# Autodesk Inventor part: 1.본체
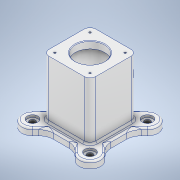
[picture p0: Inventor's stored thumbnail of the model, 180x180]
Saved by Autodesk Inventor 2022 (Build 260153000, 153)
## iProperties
Created: 2022-05
Part Number: 1.본체
Material: 알루미늄 6061
Document SubType Name: Modeling
Designer: Admin
Mass: 1072.62 g
Surface Area: 876.974 cm^2
Volume: 397.266 cm^3
Density: 2.7 g/cm^3
Appearance: 알루미늄 - 평지
Author: Admin
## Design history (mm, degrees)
sketch "스케치1"
  geometry: L1 (40, 40)-(-40, 40); L2 (-40, 40)-(-40, -40); L3 (-40, -40)-(40, -40); L4 (40, -40)-(40, 40); L5 (40, 40)-(-40, -40); L6 (-40, 40)-(40, -40); 1 further point
  constraints: 12 end point, 2 midpoint, 2 parallel, 1 horizontal, 1 perpendicular
  dimensions: "d0" = 80 distance of L3.end L2.end; "d1" = 80 distance of L2.end L1.end
extrude "돌출1" new body sketch "스케치1" distance "d2" = 110; taper "d3" = 0 deg
sketch "스케치2"
  geometry: L1 (40, 40)-(40, -40) reference; L2 (-40, 40)-(40, 40) reference; L3 (-40, -40)-(-40, 40) reference; L4 (40, -40)-(-40, -40) reference; L5 (-104.238, 0)-(104.238, 0) reference; L6 (0, -104.238)-(0, 104.238) reference; L7 (-23.544, 49)-(23.544, 49); L8 (49, 23.544)-(49, -23.544); L9 (23.544, -49)-(-23.544, -49); L10 (-49, -23.544)-(-49, 23.544); L11 (-49, 49)-(49, -49); L12 (49, 49)-(-49, -49); L13 (-49, 49)-(49, -49); L14 (-49, -49)-(49, 49); L15 (49, 23.544)-(61.728, 36.272); L16 (61.728, -36.272)-(49, -23.544); L17 (36.272, 61.728)-(23.544, 49); L18 (-23.544, 49)-(-36.272, 61.728); L19 (-61.728, 36.272)-(-49, 23.544); L20 (-49, -23.544)-(-61.728, -36.272); L21 (-36.272, -61.728)-(-23.544, -49); L22 (23.544, -49)-(36.272, -61.728); A1 r 18 centre (-49, 49) between (-36.272, 61.728) and (-61.728, 36.272); A2 r 18 centre (49, -49) between (36.272, -61.728) and (61.728, -36.272); A3 r 18 centre (-49, -49) between (-61.728, -36.272) and (-36.272, -61.728); A4 r 18 centre (49, 49) between (61.728, 36.272) and (36.272, 61.728); 1 further point
  constraints: 36 end point, 16 tangent, 12 equal length, 8 point on circle, 4 centre point, 4 midpoint, 1 horizontal, 1 perpendicular, 1 point on line
  dimensions: "d7" = 98 distance of L11.end L12.end; "d8" = 98 distance of L12.start L11.end; "d9" = 36 diameter of A2; "d10" = 36 diameter of A4; "d11" = 49 distance between parallel lines of L6 L8; "d12" = 49 distance between parallel lines of L6 L10; "d13" = 98 distance between parallel lines of L7 L9; "d14" = 49 distance between parallel lines of L7 L5; "d15" = 45 deg angle of L5 L14; "d16" = 45 deg angle of L5 L11
extrude "돌출2" join sketch "스케치2" distance "d17" = 12; taper "d18" = 0 deg
sketch "스케치3"
  geometry: L1 (-61.728, -36.272)-(-49, -23.544) reference; L2 (-49, -23.544)-(-49, 23.544) reference; L3 (-49, 23.544)-(-61.728, 36.272) reference; L4 (-36.272, 61.728)-(-23.544, 49) reference; L5 (-23.544, 49)-(23.544, 49) reference; L6 (23.544, 49)-(36.272, 61.728) reference; L7 (61.728, 36.272)-(49, 23.544) reference; L8 (49, 23.544)-(49, -23.544) reference; L9 (49, -23.544)-(61.728, -36.272) reference; L10 (36.272, -61.728)-(23.544, -49) reference; L11 (23.544, -49)-(-23.544, -49) reference; L12 (-23.544, -49)-(-36.272, -61.728) reference; A1 r 18 centre (-49, 49) between (-36.272, 61.728) and (-61.728, 36.272) reference; A2 r 18 centre (49, 49) between (61.728, 36.272) and (36.272, 61.728) reference; A3 r 18 centre (49, -49) between (36.272, -61.728) and (61.728, -36.272) reference; A4 r 18 centre (-49, -49) between (-61.728, -36.272) and (-36.272, -61.728) reference; 5 further points
  constraints: 4 coincident
hole "구멍1" sketch "스케치3" at (49, 49), (49, -49), (-49, 49), (-49, -49) diameter "d19" = 10; stored, may be unused: countersink angle "d23" = 90 deg, drill point angle "d25" = 118 deg; dims "d20" = 11, "d21" = 18, "d22" = 4, "d24" = 13
sketch "스케치4"
  geometry: L1 (40, -132)-(40, 22) reference; L2 (16.456, -98)-(63.544, -98) reference; C1 r 20 at (40, -49); 1 further point
  constraints: 1 centre point, 1 point on line
  dimensions: "d26" = 40 diameter of C1; "d27" = 49 distance from line of L2 C1.centre
extrude "돌출3" join sketch "스케치4" distance "d28" = 15; taper "d29" = 0 deg
sketch "스케치5"
  geometry: C1 r 20 at (0, 0) reference; C2 r 15 at (0, 0); 1 further point
  constraints: 1 centre point, 1 coincident
  dimensions: "d30" = 30 diameter of C2
extrude "돌출4" cut sketch "스케치5" distance "d31" = 8; taper "d32" = 0 deg
sketch "스케치6"
  geometry: L1 (-22, 0)-(132, 0) reference; L2 (0, -93.8)-(0, 93.8) reference; L3 (110, -40)-(110, 40) reference; L4 (110, -25)-(98, -25); L5 (98, -25)-(98, -35); L6 (98, -35)-(12, -35); L7 (12, -35)-(12, -25); L8 (12, -25)-(0, -25); L9 (0, 23.544)-(0, -23.544) reference; L10 (110, -25)-(110, 0); L11 (110, 0)-(0, 0); L12 (0, 0)-(0, -25); 1 further point
  constraints: 16 end point, 4 point on line, 3 perpendicular, 2 collinear, 1 horizontal, 1 midpoint
  dimensions: "d33" = 70 diameter of L6 L1; "d34" = 50 diameter of L8 L1; "d35" = 86 distance of L5.end L6.end; "d36" = 12 distance of L4.start L4.end
revolve "회전1" sketch "스케치6" stored, may be unused: angle "d37" = 90 deg
sketch "스케치7"
  geometry: C1 r 15 at (0, 0) reference; C2 r 15 at (0, 0) reference; C3 r 12.5 at (0, 0); 1 further point
  constraints: 1 centre point, 1 coincident
  dimensions: "d38" = 25 diameter of C3
extrude "돌출5" cut sketch "스케치7" stored distance "d39" = 8; taper "d40" = 0 deg
fillet "모깎기1" dims "d41" = 3
sketch "스케치8"
  geometry: L1 (0, -98)-(80, -98) reference; L2 (80, -98)-(80, 0) reference; L3 (0, 0)-(80, 0) reference; L4 (0, -98)-(0, 0) reference; L5 (40, -132)-(40, 22) reference; C1 r 20 at (40, -49) reference; 2 further points
  constraints: 1 point on line, 1 other
  dimensions: "d42" = 10 distance from line of L3 point (40, -10)
feature "엠보싱1" sketch "스케치8" dims "d0" = 80, "d1" = 80, "d7" = 98, "d8" = 98, "d9" = 36, "d10" = 36, "d11" = 49, "d12" = 49, "d13" = 98, "d14" = 49, "d15" = 45 deg, "d16" = 45 deg, "d43" = 0.5, "d44" = 0
chamfer "모따기1" distance "d45" = 1; stored, may be unused: second distance "d46" = 2, angle "d47" = 45 deg
chamfer "모따기2" distance "d48" = 1; stored, may be unused: second distance "d49" = 2, angle "d50" = 45 deg
chamfer "모따기3" distance "d51" = 1; stored, may be unused: second distance "d52" = 2, angle "d53" = 45 deg
fillet "모깎기2" dims "d54" = 10
fillet "모깎기3" dims "d55" = 3
fillet "모깎기4" dims "d56" = 3
sketch "스케치9"
  geometry: L1 (-30, -30)-(30, -30); L2 (30, -30)-(30, 30); L3 (30, 30)-(-30, 30); L4 (-30, 30)-(-30, -30); L5 (-30, -30)-(30, 30); L6 (30, -30)-(-30, 30); C1 r 35 at (0, 0) reference; A1 r 10 centre (30, -30) between (30, -40) and (40, -30) reference; 5 further points
  constraints: 12 end point, 4 coincident, 2 midpoint, 2 parallel, 1 horizontal, 1 perpendicular
  dimensions: "d57" = 60 distance of L3.end L2.end; "d58" = 60 distance of L2.end L1.end
hole "구멍2" sketch "스케치9" at (-30, 30), (30, 30), (-30, -30), (30, -30) diameter "d59" = 3.242; stored, may be unused: countersink angle "d63" = 90 deg, drill point angle "d65" = 118 deg; dims "d60" = 8, "d61" = 18, "d62" = 4, "d64" = 10
sketch "스케치10"
  geometry: L1 (30, 30)-(-30, 30); L2 (-30, 30)-(-30, -30); L3 (-30, -30)-(30, -30); L4 (30, -30)-(30, 30); L5 (30, 30)-(-30, -30); L6 (-30, 30)-(30, -30); C1 r 1.621 at (30, -30) reference; C2 r 1.621 at (-30, -30) reference; C3 r 1.621 at (-30, 30) reference; C4 r 1.621 at (30, 30) reference; A1 r 10 centre (-30, -30) between (-40, -30) and (-30, -40) reference; 5 further points
  constraints: 12 end point, 4 coincident, 2 midpoint, 2 parallel, 1 horizontal, 1 perpendicular
  dimensions: "d66" = 60 distance of L3.end L2.end (derived); "d67" = 60 distance of L2.end L1.end (derived)
hole "구멍3" sketch "스케치10" at (30, -30), (-30, -30), (-30, 30), (30, 30) diameter "d68" = 3.242; stored, may be unused: countersink angle "d72" = 90 deg, drill point angle "d74" = 118 deg; dims "d69" = 8, "d70" = 4, "d71" = 2, "d73" = 10
fillet "모깎기5" dims "d75" = 25
node "솔리드1"
node "투영된 루프1"
node "투영된 루프2"
node "투영된 루프3"
node "투영된 루프4"
node "투영된 루프5"
feature "A9D066F2-1C7D-4E18-AEED-F7BC21143FA4" dims "d19" = 10, "d20" = 11, "d21" = 18, "d22" = 4, "d23" = 90 deg, "d24" = 13, "d25" = 118 deg
